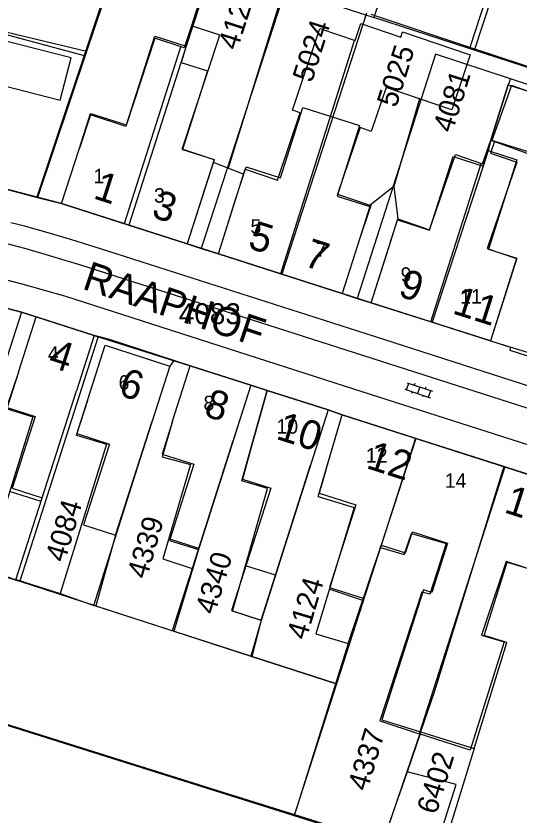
# Model space of a CAD drawing. Extents: x 148816 to 151297, y 399515 to 402500.
# Drawn here: x 150587.8 to 150631.2, y 399661.2 to 399730.1 of the extents above; entities that cross this region are included whole.
import ezdxf

# ---------------------------------------------------------------- set-up
doc = ezdxf.new("R2010")
doc.units = 0
for name, color, linetype in [('B01 Hoofdgebouw  [D] Norm', 7, 'Continuous'), ('B01 Hoofdgebouw  [T] Norm', 7, 'Continuous'), ('B01 hoofgebouw', 7, 'Continuous'), ('B02 Bijgebouw  [D] Norm', 7, 'Continuous'), ('B07 Tussenmuur  [D] Norm', 7, 'Continuous'), ('G01 perceelsgrens', 7, 'Continuous'), ('S02 Open verharding  Norm', 7, 'Continuous'), ('T04 Haag heg  [D] Gem', 7, 'Continuous'), ('V00 Kant verharding algemeen  [T] Norm', 7, 'Continuous'), ('V00 Kant verharding algemeen secundair  [T] Gem', 7, 'Continuous'), ('Z01 perceelnummer', 7, 'Continuous'), ('Z02 huisnummer', 7, 'Continuous'), ('Z02 Huisnummer  [Tekst] Norm', 7, 'Continuous'), ('Z06 straatnaam', 7, 'Continuous')]:
    doc.layers.add(name, color=color, linetype=linetype)

msp = doc.modelspace()

# ---------------------------------------------------------------- linework, layer by layer
at = {"layer": 'B01 Hoofdgebouw  [D] Norm'}
for p, q in [((150594.23, 399721.599), (150593.28, 399718.71)), ((150618.42, 399713.778), (150617.47, 399710.96)), ((150601.32, 399695.2), (150600.416, 399692.131)), ((150607.291, 399690.048), (150608.14, 399693.03)), ((150600.416, 399692.131), (150602.857, 399691.458)), ((150602.857, 399691.458), (150600.488, 399683.325)), ((150589.974, 399688.266), (150587.258, 399689.139)), ((150603.578, 399684.225), (150600.991, 399685.051)), ((150600.488, 399683.325), (150603.023, 399682.485)), ((150630.092, 399683.089), (150627.967, 399676.759)), ((150632.864, 399682.189), (150630.092, 399683.089)), ((150610.206, 399681.912), (150607.607, 399682.736)), ((150617.727, 399679.737), (150614.846, 399680.711)), ((150627.967, 399676.759), (150629.925, 399676.16)), ((150629.925, 399676.16), (150627.004, 399666.831)), ((150627.004, 399666.831), (150622.605, 399668.256)), ((150621.556, 399664.977), (150619.405, 399658.825)), ((150625.801, 399663.881), (150621.556, 399664.977)), ((150623.753, 399657.552), (150625.801, 399663.881))]:
    msp.add_line(p, q, dxfattribs=at)
for points in [[(150604.908, 399717.724), (150602.16, 399718.626), (150605.388, 399728.461), (150602.941, 399729.264), (150602.317, 399727.364), (150599.794, 399728.192), (150597.295, 399720.591), (150594.23, 399721.599)], [(150607.597, 399716.912), (150610.377, 399715.974), (150612.327, 399721.755), (150611.657, 399721.981), (150614.032, 399729.023), (150617.062, 399727.998), (150617.556, 399729.459), (150621.004, 399728.292), (150621.155, 399728.738), (150627.008, 399726.762), (150625.41, 399722.028), (150619.738, 399723.943), (150618.462, 399720.163), (150617.493, 399720.49), (150615.555, 399714.743), (150618.42, 399713.778)], [(150620.75, 399712.625), (150623.492, 399711.684), (150625.717, 399718.167), (150628.066, 399717.36), (150628.772, 399719.416), (150629.104, 399719.302), (150628.76, 399718.299), (150631.03, 399717.52), (150628.474, 399710.073), (150631.007, 399709.204)], [(150588.02, 399699.42), (150586.963, 399696.278), (150589.252, 399695.553), (150585.183, 399682.463), (150587.803, 399681.511), (150593.04, 399697.81)], [(150593.025, 399693.977), (150595.612, 399693.199), (150591.618, 399680.337), (150594.517, 399679.311), (150599.56, 399695.18)], [(150613.19, 399691.331), (150608.97, 399678.011), (150606.478, 399678.811), (150609.519, 399689.384), (150607.288, 399690.038)], [(150613.889, 399688.697), (150616.992, 399687.745), (150613.673, 399676.867), (150616.47, 399676.018), (150619.27, 399684.305), (150621.304, 399683.706), (150621.929, 399685.511), (150624.93, 399684.637), (150623.531, 399680.291), (150622.819, 399680.465), (150619.197, 399669.356), (150622.605, 399668.256)]]:
    msp.add_lwpolyline(points, dxfattribs=at)
msp.add_lwpolyline([(150634.223, 399722.828), (150630.56, 399724.129), (150628.869, 399719.369), (150632.531, 399718.068)], close=True, dxfattribs=at)
at = {"layer": 'B01 Hoofdgebouw  [T] Norm'}
for p, q in [((150591.75, 399713.95), (150593.28, 399718.71)), ((150604.908, 399717.724), (150602.58, 399710.48)), ((150605.27, 399709.61), (150607.597, 399716.912)), ((150602.58, 399710.48), (150591.75, 399713.95)), ((150618.46, 399705.39), (150620.75, 399712.625)), ((150617.47, 399710.96), (150615.95, 399706.2)), ((150615.95, 399706.2), (150605.27, 399709.61)), ((150631.007, 399709.204), (150628.75, 399702.12)), ((150583.73, 399705.77), (150588.3, 399704.58)), ((150628.75, 399702.12), (150618.46, 399705.39)), ((150588.3, 399704.58), (150585.53, 399696.08)), ((150588.02, 399699.42), (150589.55, 399704.18)), ((150589.55, 399704.18), (150594.57, 399702.57)), ((150594.57, 399702.57), (150593.04, 399697.81)), ((150593.025, 399693.977), (150595.52, 399701.74)), ((150595.52, 399701.74), (150601.09, 399699.94)), ((150601.09, 399699.94), (150599.56, 399695.18)), ((150601.32, 399695.2), (150602.84, 399699.96)), ((150602.84, 399699.96), (150608.07, 399698.29)), ((150608.07, 399698.29), (150603.023, 399682.485)), ((150609.49, 399697.84), (150608.14, 399693.03)), ((150609.49, 399697.84), (150614.74, 399696.16)), ((150614.74, 399696.16), (150613.22, 399691.4)), ((150613.889, 399688.697), (150615.95, 399695.75)), ((150615.95, 399695.75), (150635.33, 399689.53))]:
    msp.add_line(p, q, dxfattribs=at)
at = {"layer": 'B01 hoofgebouw'}
for points in [[(150593.28, 399718.71), (150594.245, 399721.713), (150597.341, 399720.721), (150599.795, 399728.381), (150602.501, 399727.514), (150602.05, 399726.106), (150604.34, 399725.373), (150602.173, 399718.611), (150604.912, 399717.734), (150604.11, 399715.24)], [(150632.748, 399718.174), (150628.776, 399719.422), (150630.266, 399724.163), (150634.238, 399722.915), (150632.748, 399718.174)], [(150606.79, 399714.38), (150607.658, 399717.105), (150610.63, 399716.156), (150612.568, 399722.226), (150617.455, 399720.665), (150615.517, 399714.595), (150618.343, 399713.693), (150617.47, 399710.96)], [(150604.11, 399715.24), (150602.58, 399710.48), (150591.75, 399713.95), (150593.28, 399718.71)], [(150619.97, 399710.16), (150620.723, 399712.538), (150623.502, 399711.655), (150625.516, 399717.993), (150628.123, 399717.165), (150628.548, 399718.504), (150631.033, 399717.714), (150628.587, 399710.018), (150631.02, 399709.245), (150630.27, 399706.89)], [(150617.47, 399710.96), (150615.95, 399706.2), (150605.27, 399709.61), (150606.79, 399714.38)], [(150565.76, 399710.35), (150574.6, 399708.11), (150573.43, 399703.49), (150582.1, 399700.84), (150583.73, 399705.77), (150588.3, 399704.58), (150585.53, 399696.08), (150573.36, 399700.05), (150572.57, 399700.69)], [(150630.27, 399706.89), (150628.75, 399702.12), (150618.46, 399705.39), (150619.97, 399710.16)], [(150588.02, 399699.42), (150589.55, 399704.18), (150594.57, 399702.57), (150593.04, 399697.81)], [(150593.99, 399696.98), (150595.52, 399701.74), (150601.09, 399699.94), (150599.56, 399695.18)], [(150601.32, 399695.2), (150602.84, 399699.96), (150608.07, 399698.29), (150606.55, 399693.53)], [(150588.02, 399699.42), (150587.04, 399696.371), (150589.454, 399695.596), (150587.473, 399689.417), (150590.074, 399688.583), (150593.04, 399697.81)], [(150608.14, 399693.03), (150609.49, 399697.84), (150614.74, 399696.16), (150613.22, 399691.4)], [(150593.99, 399696.98), (150593.072, 399694.125), (150595.879, 399693.218), (150593.628, 399686.251), (150596.402, 399685.354), (150599.56, 399695.18)], [(150614.55, 399690.96), (150615.95, 399695.75), (150635.33, 399689.53), (150633.8, 399684.77)], [(150601.32, 399695.2), (150600.412, 399692.356), (150603.159, 399691.479), (150601.063, 399684.917), (150603.546, 399684.124), (150606.55, 399693.53)], [(150608.14, 399693.03), (150607.347, 399690.206), (150609.795, 399689.423), (150606.417, 399678.864), (150608.957, 399678.051), (150613.22, 399691.4)], [(150614.55, 399690.96), (150613.974, 399688.99), (150617.135, 399687.976), (150614.852, 399680.861), (150617.841, 399679.902), (150619.32, 399684.508), (150621.424, 399683.833), (150622.01, 399685.659), (150625.048, 399684.684), (150623.677, 399680.414), (150622.96, 399680.644), (150619.372, 399669.457)], [(150619.372, 399669.457), (150627.35, 399666.992), (150630.167, 399676.106), (150628.218, 399676.709), (150630.178, 399683.053), (150633.054, 399682.164), (150633.8, 399684.77)]]:
    msp.add_lwpolyline(points, dxfattribs=at)
at = {"layer": 'B02 Bijgebouw  [D] Norm'}
msp.add_lwpolyline([(150585.672, 399724.392), (150591.638, 399722.869), (150592.567, 399726.507), (150586.601, 399728.03)], close=True, dxfattribs=at)
at = {"layer": 'B07 Tussenmuur  [D] Norm'}
for p, q in [((150616.983, 399727.971), (150610.633, 399707.898)), ((150616.983, 399727.971), (150610.633, 399707.898)), ((150597.165, 399712.215), (150602.047, 399727.451)), ((150597.165, 399712.215), (150602.047, 399727.451)), ((150623.605, 399703.755), (150627.941, 399717.4)), ((150623.605, 399703.755), (150627.941, 399717.4)), ((150622.29, 399693.715), (150619.27, 399684.305)), ((150622.29, 399693.715), (150619.27, 399684.305)), ((150629.987, 399691.245), (150622.608, 399668.255)), ((150629.987, 399691.245), (150622.608, 399668.255))]:
    msp.add_line(p, q, dxfattribs=at)
at = {"layer": 'G01 perceelsgrens'}
for points in [[(150635.313, 399752.934), (150626.982, 399727.404)], [(150597.327, 399737.205), (150593.91, 399727.057)], [(150604.865, 399734.722), (150602.501, 399727.514), (150597.556, 399712.09)], [(150593.91, 399727.057), (150569.86, 399732.829)], [(150611.122, 399732.649), (150603.803, 399710.084)], [(150618.039, 399730.359), (150610.749, 399707.86)], [(150626.982, 399727.404), (150618.445, 399730.225)], [(150593.91, 399727.057), (150589.675, 399714.481)], [(150636.241, 399724.344), (150626.982, 399727.404)], [(150630.485, 399724.681), (150624.008, 399726.825), (150617.261, 399705.777)], [(150630.485, 399724.681), (150630.266, 399724.163), (150628.776, 399719.422), (150628.548, 399718.504), (150628.123, 399717.165), (150623.705, 399703.723)], [(150638.563, 399722.006), (150630.485, 399724.681)], [(150566.525, 399720.322), (150569.26, 399719.69), (150579.58, 399717.13), (150589.675, 399714.481)], [(150589.675, 399714.481), (150591.75, 399713.95), (150597.556, 399712.09)], [(150597.556, 399712.09), (150602.58, 399710.48), (150603.803, 399710.084)], [(150588.3, 399704.58), (150583.73, 399705.77), (150574.6, 399708.11), (150565.76, 399710.35), (150564.218, 399710.822)], [(150603.803, 399710.084), (150605.27, 399709.61), (150610.749, 399707.86)], [(150610.749, 399707.86), (150615.95, 399706.2), (150617.261, 399705.777)], [(150617.261, 399705.777), (150618.46, 399705.39), (150623.705, 399703.723)], [(150588.3, 399704.58), (150585.53, 399696.08)], [(150594.904, 399702.485), (150594.57, 399702.57), (150588.3, 399704.58)], [(150623.705, 399703.723), (150628.75, 399702.12), (150640.655, 399698.442)], [(150594.904, 399702.485), (150588.145, 399681.393)], [(150601.426, 399700.425), (150595.867, 399702.241), (150594.904, 399702.485)], [(150601.426, 399700.425), (150601.09, 399699.94), (150596.402, 399685.354), (150594.711, 399679.267)], [(150608.07, 399698.29), (150602.84, 399699.96), (150601.426, 399700.425)], [(150608.07, 399698.29), (150603.546, 399684.124), (150601.442, 399677.087)], [(150614.74, 399696.16), (150609.49, 399697.84), (150608.07, 399698.29)], [(150614.74, 399696.16), (150608.957, 399678.051), (150608.148, 399674.916)], [(150622.123, 399693.769), (150615.95, 399695.75), (150614.74, 399696.16)], [(150622.306, 399693.71), (150619.32, 399684.508), (150615.473, 399672.544)], [(150622.306, 399693.71), (150622.123, 399693.769)], [(150629.895, 399691.274), (150622.306, 399693.71)], [(150629.895, 399691.274), (150623.889, 399671.828), (150622.724, 399668.421)], [(150650.468, 399684.564), (150635.33, 399689.53), (150629.895, 399691.274)], [(150581.742, 399683.433), (150587.833, 399681.494), (150588.145, 399681.393)], [(150588.145, 399681.393), (150594.711, 399679.267)], [(150594.711, 399679.267), (150601.442, 399677.087)], [(150601.442, 399677.087), (150608.148, 399674.916)], [(150608.148, 399674.916), (150615.473, 399672.544)], [(150615.473, 399672.544), (150611.853, 399661.295)], [(150578.646, 399671.687), (150605.671, 399663.23), (150611.853, 399661.295)], [(150622.724, 399668.421), (150619.472, 399658.911)], [(150622.724, 399668.421), (150627.35, 399666.992), (150624.383, 399657.394)], [(150611.853, 399661.295), (150619.472, 399658.911)]]:
    msp.add_lwpolyline(points, dxfattribs=at)
at = {"layer": 'S02 Open verharding  Norm'}
for p, q in [((150621.505, 399697.888), (150621.693, 399698.458)), ((150621.551, 399698.505), (150623.735, 399697.785)), ((150622.215, 399698.444), (150622.168, 399698.301)), ((150622.643, 399698.145), (150622.455, 399697.575)), ((150623.165, 399698.131), (150623.118, 399697.988)), ((150621.363, 399697.935), (150623.547, 399697.215)), ((150621.98, 399697.732), (150621.933, 399697.589)), ((150622.93, 399697.419), (150622.883, 399697.276)), ((150623.405, 399697.262), (150623.593, 399697.832))]:
    msp.add_line(p, q, dxfattribs=at)
at = {"layer": 'T04 Haag heg  [D] Gem'}
for p, q in [((150627.366, 399727.158), (150634.877, 399750)), ((150597.132, 399737.011), (150589.605, 399714.51)), ((150604.632, 399734.567), (150602.941, 399729.264)), ((150571.433, 399732.673), (150593.685, 399726.708)), ((150610.926, 399732.516), (150606.128, 399716.993)), ((150639.273, 399723.277), (150618.694, 399729.984)), ((150622.628, 399722.967), (150620.4, 399715.425)), ((150604.837, 399717.502), (150607.456, 399716.47)), ((150620.4, 399715.425), (150618.367, 399713.795)), ((150620.4, 399715.425), (150620.75, 399712.625)), ((150603.023, 399682.485), (150601.291, 399677.128)), ((150587.818, 399681.558), (150591.618, 399680.337)), ((150615.389, 399672.583), (150594.517, 399679.311)), ((150557.756, 399678.168), (150619.405, 399658.825)), ((150608.97, 399678.011), (150608.082, 399674.939)), ((150616.47, 399676.018), (150611.976, 399661.733)), ((150622.681, 399668.231), (150621.556, 399664.977))]:
    msp.add_line(p, q, dxfattribs=at)
at = {"layer": 'V00 Kant verharding algemeen  [T] Norm'}
for p, q in [((150597.132, 399737.011), (150618.694, 399729.984)), ((150619.206, 399731.533), (150618.694, 399729.984)), ((150591.75, 399713.95), (150579.58, 399717.13)), ((150605.27, 399709.61), (150602.58, 399710.48)), ((150618.46, 399705.39), (150615.95, 399706.2)), ((150588.3, 399704.58), (150589.55, 399704.18)), ((150594.57, 399702.57), (150602.84, 399699.96)), ((150628.75, 399702.12), (150630.49, 399701.56)), ((150630.49, 399701.56), (150630.42, 399701.31)), ((150630.42, 399701.31), (150640.21, 399698.11)), ((150608.07, 399698.29), (150609.49, 399697.84)), ((150614.74, 399696.16), (150615.95, 399695.75))]:
    msp.add_line(p, q, dxfattribs=at)
for points in [[(150566.915, 399712.556), (150588.315, 399707.022), (150590.358, 399706.462), (150592.009, 399705.984), (150616.937, 399697.974), (150634.098, 399692.478), (150637.027, 399691.635), (150637.344, 399691.557)], [(150588.557, 399711.987), (150587.97, 399712.138), (150587.381, 399712.281)], [(150592.631, 399710.807), (150590.598, 399711.412), (150588.557, 399711.987)], [(150596.466, 399709.618), (150594.551, 399710.221), (150592.631, 399710.807)], [(150639.172, 399694.151), (150637.812, 399694.604), (150636.504, 399696.77), (150618.745, 399702.481), (150596.466, 399709.618)]]:
    msp.add_lwpolyline(points, dxfattribs=at)
at = {"layer": 'V00 Kant verharding algemeen secundair  [T] Gem'}
msp.add_lwpolyline([(150637.759, 399694.439), (150593.419, 399708.649), (150588.701, 399710.034), (150571.049, 399714.612)], dxfattribs=at)

# ---------------------------------------------------------------- texts
at = {"layer": 'Z01 perceelnummer'}
for s, rotation, p in [('4121', 72.21817, (150606.911, 399727.087)), ('5024', 72.32992, (150613.34, 399724.292)), ('5025', 72.43973, (150620.615, 399722.138)), ('4081', 72.54967, (150625.454, 399719.964)), ('4084', 73.5877, (150592.021, 399682.949)), ('4339', 73.75363, (150599.085, 399681.512)), ('4340', 73.30076, (150604.963, 399678.448)), ('4124', 73.38335, (150612.851, 399676.257)), ('4337', 73.2401, (150618.114, 399663.23)), ('6402', 72.96489, (150624.076, 399661.223))]:
    msp.add_text(s, height=1.8, rotation=rotation, dxfattribs=at).set_placement(p)
msp.add_text('4083', height=1.8, dxfattribs=at).set_placement((150601.861, 399703.553))
at = {"layer": 'Z02 huisnummer'}
for s, rotation, p in [('1', 342.23568, (150594.393, 399714.416)), ('3', 342.23568, (150599.405, 399712.81)), ('5', 342.3077, (150607.722, 399710.139)), ('7', 342.3077, (150612.535, 399708.601)), ('9', 342.36228, (150620.685, 399705.994)), ('11', 342.36228, (150625.378, 399704.502)), ('4', 342.23568, (150590.488, 399699.94)), ('6', 342.05444, (150596.548, 399697.467)), ('8', 342.3077, (150603.917, 399695.679)), ('10', 342.23568, (150610.153, 399693.69)), ('12', 342.18111, (150617.931, 399691.175)), ('16', 342.18111, (150629.831, 399687.355))]:
    msp.add_text(s, height=2.5, rotation=rotation, dxfattribs=at).set_placement(p)
at = {"layer": 'Z02 Huisnummer  [Tekst] Norm'}
for s, p in [('1', (150594.5, 399715.695)), ('3', (150599.72, 399714.02)), ('5', (150608.045, 399711.35)), ('7', (150613.697, 399709.355)), ('9', (150621, 399707.205)), ('11', (150626.14, 399705.319)), ('4', (150590.56, 399700.39)), ('6', (150596.665, 399697.9)), ('8', (150603.99, 399696.13)), ('10', (150610.295, 399694.115)), ('12', (150618.005, 399691.625)), ('14', (150624.811, 399689.448))]:
    msp.add_text(s, height=1.25, dxfattribs=at).set_placement(p)
at = {"layer": 'Z06 straatnaam'}
msp.add_text('RAAPHOF', height=2.5, rotation=341.58317, dxfattribs=at).set_placement((150593.443, 399706.631))

doc.saveas('drawing.dxf')
